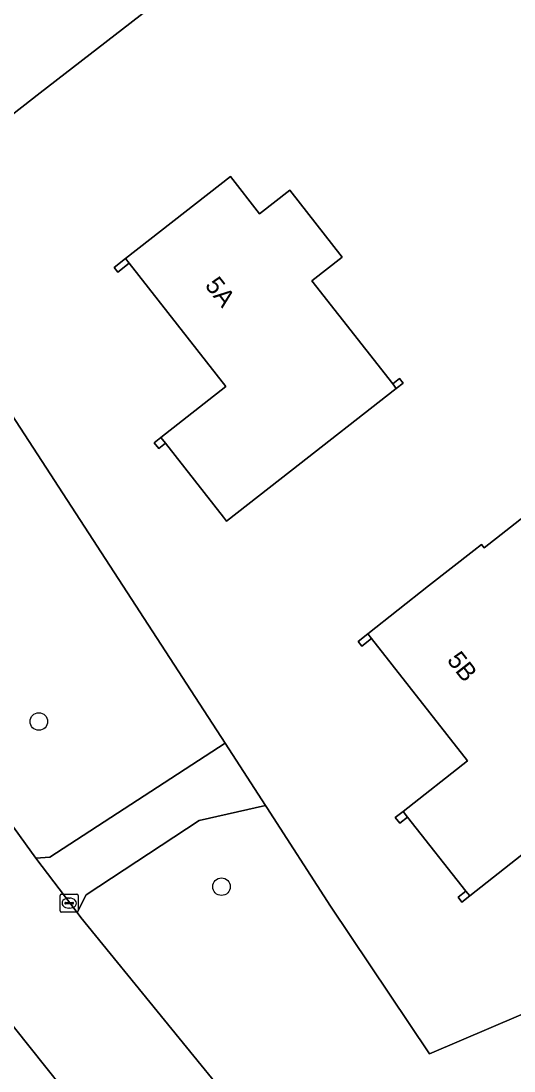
# Model space of a CAD drawing. Extents: x 162417 to 163722, y 384268 to 385417.
# Drawn here: x 163382.9 to 163410.4, y 384907 to 384965.6 of the extents above; entities that cross this region are included whole.
import ezdxf

# ---------------------------------------------------------------- set-up
doc = ezdxf.new("R2010")
doc.units = 0
for name, color, linetype in [('IMGEO_Boom', 7, 'Continuous'), ('IMGEO_Erf', 7, 'Continuous'), ('IMGEO_Groenvoorziening', 7, 'Continuous'), ('IMGEO_Kolk', 7, 'Continuous'), ('IMGEO_Loofbos', 7, 'Continuous'), ('IMGEO_Muur', 7, 'Continuous'), ('IMGEO_Pand', 7, 'Continuous'), ('IMGEO_Pand_nummerreeks', 7, 'Continuous'), ('IMGEO_Rijbaan_lokaal_gesloten', 7, 'Continuous'), ('IMGEO_Voetpad_open', 7, 'Continuous')]:
    doc.layers.add(name, color=color, linetype=linetype)

msp = doc.modelspace()

# ---------------------------------------------------------------- linework, layer by layer
at = {"layer": 'IMGEO_Boom'}
for centre in [(163383.916, 384926.502), (163394.091, 384917.293)]:
    msp.add_circle(centre, 0.489, dxfattribs=at)
at = {"layer": 'IMGEO_Erf'}
for points in [[(163383.993, 384961.544), (163380.314, 384958.697), (163380.225, 384958.812), (163376.874, 384963.141), (163376.718, 384963.343), (163380.414, 384966.203), (163375.046, 384973.139), (163374.9, 384973.327), (163380.856, 384977.937), (163381.023, 384977.723), (163381.669, 384976.895), (163385.708, 384980.043), (163391.542, 384972.558), (163387.465, 384969.38), (163389.817, 384966.363), (163389.969, 384966.169)], [(163403.626, 384945.323), (163404.007, 384945.622), (163404.202, 384945.373), (163403.821, 384945.074), (163397.939, 384940.465), (163394.375, 384937.672), (163394.196, 384937.9), (163390.965, 384942.023), (163390.594, 384941.732), (163390.346, 384942.048), (163390.717, 384942.339), (163394.335, 384945.174), (163388.946, 384952.051), (163388.32, 384951.56), (163388.119, 384951.816), (163388.745, 384952.307), (163392.055, 384954.901), (163394.587, 384956.885), (163396.213, 384954.81), (163397.887, 384956.123), (163400.806, 384952.398), (163399.118, 384951.075)]]:
    msp.add_lwpolyline(points, close=True, dxfattribs=at)
for points in [[(163366.55, 384967.171), (163368.242, 384964.531), (163368.391, 384964.299), (163379.349, 384947.426), (163379.982, 384947.768), (163380.971, 384945.978), (163382.418, 384943.603), (163394.29, 384925.305), (163394.506, 384924.972), (163396.543, 384921.829), (163396.623, 384921.705), (163400.169, 384916.215), (163405.67, 384907.984), (163444.074, 384924.391), (163451.907, 384927.667), (163452.25, 384927.811), (163454.895, 384928.917), (163476.005, 384937.8), (163477.129, 384938.273), (163479.466, 384939.261), (163494.207, 384945.241)], [(163410.809, 384919.065), (163407.912, 384916.786), (163407.471, 384916.44), (163407.262, 384916.706), (163407.702, 384917.053), (163404.458, 384921.178), (163404.018, 384920.832), (163403.769, 384921.148), (163404.209, 384921.494), (163407.8, 384924.319), (163402.449, 384931.123), (163401.906, 384930.697), (163401.693, 384930.967), (163402.236, 384931.394), (163405.623, 384934.059), (163408.14, 384936.038), (163408.572, 384936.378), (163408.727, 384936.181), (163411.392, 384938.277)]]:
    msp.add_lwpolyline(points, dxfattribs=at)
at = {"layer": 'IMGEO_Groenvoorziening'}
msp.add_lwpolyline([(163382.418, 384943.603), (163373.08, 384937.416), (163372.231, 384936.23), (163372.616, 384935.569), (163375.046, 384931.395), (163375.106, 384931.292), (163380.184, 384923.814), (163383.749, 384918.881), (163384.526, 384918.935), (163394.29, 384925.305)], close=True, dxfattribs=at)
msp.add_lwpolyline([(163451.907, 384927.667), (163444.074, 384924.391), (163405.67, 384907.984), (163400.169, 384916.215), (163396.623, 384921.705), (163396.543, 384921.829), (163392.848, 384920.991), (163386.542, 384916.841), (163386.043, 384915.852), (163386.251, 384915.578), (163400.236, 384898.404)], dxfattribs=at)
at = {"layer": 'IMGEO_Kolk'}
for p, q in [((163385.106, 384915.952), (163385.106, 384916.804)), ((163385.181, 384916.878), (163386.033, 384916.878)), ((163385.365, 384916.372), (163385.365, 384916.384)), ((163385.408, 384916.421), (163385.806, 384916.421)), ((163385.594, 384916.658), (163385.619, 384916.658)), ((163385.849, 384916.384), (163385.849, 384916.372)), ((163386.107, 384916.804), (163386.107, 384915.952)), ((163386.033, 384915.878), (163385.181, 384915.878)), ((163385.803, 384916.335), (163385.405, 384916.335)), ((163385.617, 384916.098), (163385.592, 384916.098))]:
    msp.add_line(p, q, dxfattribs=at)
for points in [[(163385.106, 384915.952), (163385.106, 384916.804)], [(163385.181, 384916.878), (163386.033, 384916.878)], [(163386.107, 384916.804), (163386.107, 384915.952)], [(163386.033, 384915.878), (163385.181, 384915.878)]]:
    msp.add_lwpolyline(points, dxfattribs=at)
for centre, radius, start, end in [((163385.183, 384916.802), 0.0765, 91.55205, 178.44795), ((163385.183, 384916.802), 0.0765, 91.55205, 178.44795), ((163385.405, 384916.381), 0.0403, 85.87752, 175.75265), ((163385.402, 384916.371), 0.0366, 178.93798, 274.71019), ((163385.806, 384916.378), 0.043, 264.86636, 352.45326), ((163385.81, 384916.383), 0.0386, 1.73085, 96.63898), ((163386.031, 384916.802), 0.0765, 1.55205, 88.44795), ((163386.031, 384916.802), 0.0765, 1.55205, 88.44795), ((163385.183, 384915.954), 0.0765, 181.55205, 268.44795), ((163385.183, 384915.954), 0.0765, 181.55205, 268.44795), ((163386.031, 384915.954), 0.0765, 271.55205, 358.44795), ((163386.031, 384915.954), 0.0765, 271.55205, 358.44795)]:
    msp.add_arc(centre, radius, start, end, dxfattribs=at)
for centre, major_axis, ratio, start_param, end_param in [((163385.593, 384916.378), (-0.387, 0.002), 0.722429, 4.712389, 7.853982), ((163385.618, 384916.378), (-0.39, 0.002), 0.717154, 1.570796, 4.712389)]:
    msp.add_ellipse(centre, major_axis=major_axis, ratio=ratio, start_param=start_param, end_param=end_param, dxfattribs=at)
at = {"layer": 'IMGEO_Loofbos'}
msp.add_lwpolyline([(163387.873, 384902.747), (163381.659, 384910.522), (163375.211, 384919.101), (163369.3, 384927.939), (163367.462, 384930.688)], dxfattribs=at)
at = {"layer": 'IMGEO_Muur'}
for points in [[(163388.946, 384952.051), (163388.745, 384952.307), (163388.119, 384951.816), (163388.32, 384951.56)], [(163403.626, 384945.323), (163403.821, 384945.074), (163404.202, 384945.373), (163404.007, 384945.622)], [(163390.965, 384942.023), (163390.717, 384942.339), (163390.346, 384942.048), (163390.594, 384941.732)], [(163402.449, 384931.123), (163402.236, 384931.394), (163401.693, 384930.967), (163401.906, 384930.697)], [(163404.458, 384921.178), (163404.209, 384921.494), (163403.769, 384921.148), (163404.018, 384920.832)], [(163407.702, 384917.053), (163407.262, 384916.706), (163407.471, 384916.44), (163407.912, 384916.786)]]:
    msp.add_lwpolyline(points, close=True, dxfattribs=at)
at = {"layer": 'IMGEO_Pand'}
for points in [[(163383.993, 384961.544), (163389.969, 384966.169), (163389.817, 384966.363), (163387.465, 384969.38), (163391.542, 384972.558), (163385.708, 384980.043), (163381.669, 384976.895), (163381.023, 384977.723), (163380.856, 384977.937), (163374.9, 384973.327), (163375.046, 384973.139), (163380.414, 384966.203), (163376.718, 384963.343), (163376.874, 384963.141), (163380.225, 384958.812), (163380.314, 384958.697)], [(163397.939, 384940.465), (163403.821, 384945.074), (163403.626, 384945.323), (163399.118, 384951.075), (163400.806, 384952.398), (163397.887, 384956.123), (163396.213, 384954.81), (163394.587, 384956.885), (163392.055, 384954.901), (163388.745, 384952.307), (163388.946, 384952.051), (163394.335, 384945.174), (163390.717, 384942.339), (163390.965, 384942.023), (163394.196, 384937.9), (163394.375, 384937.672)]]:
    msp.add_lwpolyline(points, close=True, dxfattribs=at)
msp.add_lwpolyline([(163420.75, 384925.106), (163418.994, 384927.373), (163416.77, 384930.013), (163415.409, 384931.258), (163416.336, 384931.988), (163411.392, 384938.277), (163408.727, 384936.181), (163408.572, 384936.378), (163408.14, 384936.038), (163405.623, 384934.059), (163402.236, 384931.394), (163402.449, 384931.123), (163407.8, 384924.319), (163404.209, 384921.494), (163404.458, 384921.178), (163407.702, 384917.053), (163407.912, 384916.786), (163410.809, 384919.065), (163411.25, 384918.474), (163412.021, 384918.12), (163412.898, 384917.909), (163413.776, 384917.975), (163414.621, 384918.253), (163416.108, 384919.38)], dxfattribs=at)
at = {"layer": 'IMGEO_Rijbaan_lokaal_gesloten'}
msp.add_lwpolyline([(163432.532, 384858.437), (163413.249, 384882.384), (163411.476, 384884.508), (163400.236, 384898.404), (163386.251, 384915.578), (163386.043, 384915.852), (163383.749, 384918.881), (163380.184, 384923.814), (163375.106, 384931.292), (163375.046, 384931.395), (163369.3, 384927.939), (163375.211, 384919.101), (163381.659, 384910.522), (163387.873, 384902.747), (163392.297, 384897.285), (163397.987, 384890.109), (163402.83, 384884.23), (163402.899, 384884.147), (163405.013, 384881.518), (163406.766, 384879.335), (163446.26, 384830.213)], dxfattribs=at)
at = {"layer": 'IMGEO_Voetpad_open'}
msp.add_lwpolyline([(163396.543, 384921.829), (163394.506, 384924.972), (163394.29, 384925.305), (163384.526, 384918.935), (163383.749, 384918.881), (163386.043, 384915.852), (163386.542, 384916.841), (163392.848, 384920.991)], close=True, dxfattribs=at)

# ---------------------------------------------------------------- texts
at = {"layer": 'IMGEO_Pand_nummerreeks'}
for s, rotation, p in [('5A', 308.08429, (163393.127, 384950.8)), ('5B', 308.1817, (163406.608, 384929.912))]:
    msp.add_text(s, height=1, rotation=rotation, dxfattribs=at).set_placement(p)

doc.saveas('drawing.dxf')
